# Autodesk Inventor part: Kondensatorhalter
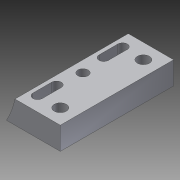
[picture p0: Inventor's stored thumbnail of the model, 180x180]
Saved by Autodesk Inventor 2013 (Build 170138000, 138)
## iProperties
Created: 2012-08
Part Number: Kondensatorhalter
Material: Aluminium 6061
Document SubType Name: Modeling
Designer: rYan
Density: 2.71 g/cm^3
Mass: 5.14408 g
Surface Area: 16.3589 cm^2
Volume: 1.89819 cm^3
Author: rYan
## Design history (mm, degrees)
sketch "Skizze1"
  geometry: L1 (2.275, 0)-(-12, 0); L2 (-12, 0)-(-12, 6); L3 (-12, 6)-(0, 6); L4 (-18.319, 0)-(25.915, 0) reference; L5 (0, -2.11)-(0, 12.018) reference; A1 r 20 centre (19.596, 10) between (0, 6) and (2.275, 0); 1 further point
  constraints: 6 end point, 2 point on circle, 1 centre point, 1 collinear, 1 horizontal, 1 parallel, 1 perpendicular, 1 point on line
  dimensions: "d0" = 12 distance of L2.end L3.end; "d2" = 6 distance of L1.end L2.end; "d3" = 20 radius of A1; "d4" = 10 distance from line of A1.centre L4
extrude "Extrusion1" new body sketch "Skizze1" distance "d5" = 30; taper "d6" = 0 deg
sketch "Skizze2"
  geometry: L1 (0, 0)-(0, 30) reference; L2 (0, 0)-(14.275, 0) reference; L3 (4, 26)-(4, 4); L4 (0, 30)-(14.275, 30) reference; L5 (14.275, 0)-(14.275, 30) reference; L6 (0, 15)-(14.275, 15); 1 further point
  constraints: 4 end point, 2 midpoint, 1 perpendicular, 1 symmetric about line
  dimensions: "d8" = 4 distance between parallel lines of L1 L3; "d17" = 22 distance of L3.start L3.end
hole "Bohrung1" sketch "Skizze2" at (4, 4), (4, 26) diameter "d10" = 3.2; stored, may be unused: countersink angle "d14" = 90 deg, drill point angle "d16" = 118 deg; dims "d11" = 6, "d12" = 5.7, "d13" = 2, "d15" = 8
sketch "Skizze3"
  geometry: L1 (12, 0)-(12, 30) reference; L2 (0, 30)-(12, 30) reference; L3 (0, 0)-(12, 0) reference; L4 (0, 0)-(0, 30) reference; L5 (12, 15)-(0, 15); L6 (3.5, 26.25)-(3.5, 21.25); L7 (1, 21.25)-(1, 26.25); L8 (3.5, 8.75)-(3.5, 3.75); L9 (1, 3.75)-(1, 8.75); A1 r 1.25 centre (2.25, 26.25) between (3.5, 26.25) and (1, 26.25); A2 r 1.25 centre (2.25, 21.25) between (1, 21.25) and (3.5, 21.25); A3 r 1.25 centre (2.25, 8.75) between (3.5, 8.75) and (1, 8.75); A4 r 1.25 centre (2.25, 3.75) between (1, 3.75) and (3.5, 3.75)
  constraints: 10 end point, 8 point on circle, 8 tangent, 4 centre point, 2 midpoint, 2 parallel, 1 vertical, 4 other
  dimensions: "d18" = 5 distance of A2.centre A1.centre; "d20" = 8.5 distance between parallel lines of L1 L6; "d21" = 2.5 distance between parallel lines of L7 L6; "d22" = 10 dimension on A3 A2
extrude "Extrusion2" cut sketch "Skizze3" stored distance "d23" = 40; taper "d24" = 0 deg
sketch "Skizze4"
  geometry: L1 (14.275, 0)-(14.275, 30) reference; L2 (0, 0)-(0, 30) reference; L3 (0, 15)-(14.275, 15); 2 further points
  constraints: 2 end point, 2 midpoint, 1 point on line
  dimensions: "d26" = 9 distance from line of L2 point (9, 15)
hole "Bohrung2" sketch "Skizze4" at (9, 15) diameter "d27" = 2.7; stored, may be unused: countersink angle "d31" = 90 deg, drill point angle "d33" = 118 deg; dims "d28" = 6, "d29" = 4.7, "d30" = 2.5, "d32" = 8
node "Volumenkörper1"
